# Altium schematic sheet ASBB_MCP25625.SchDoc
size A4
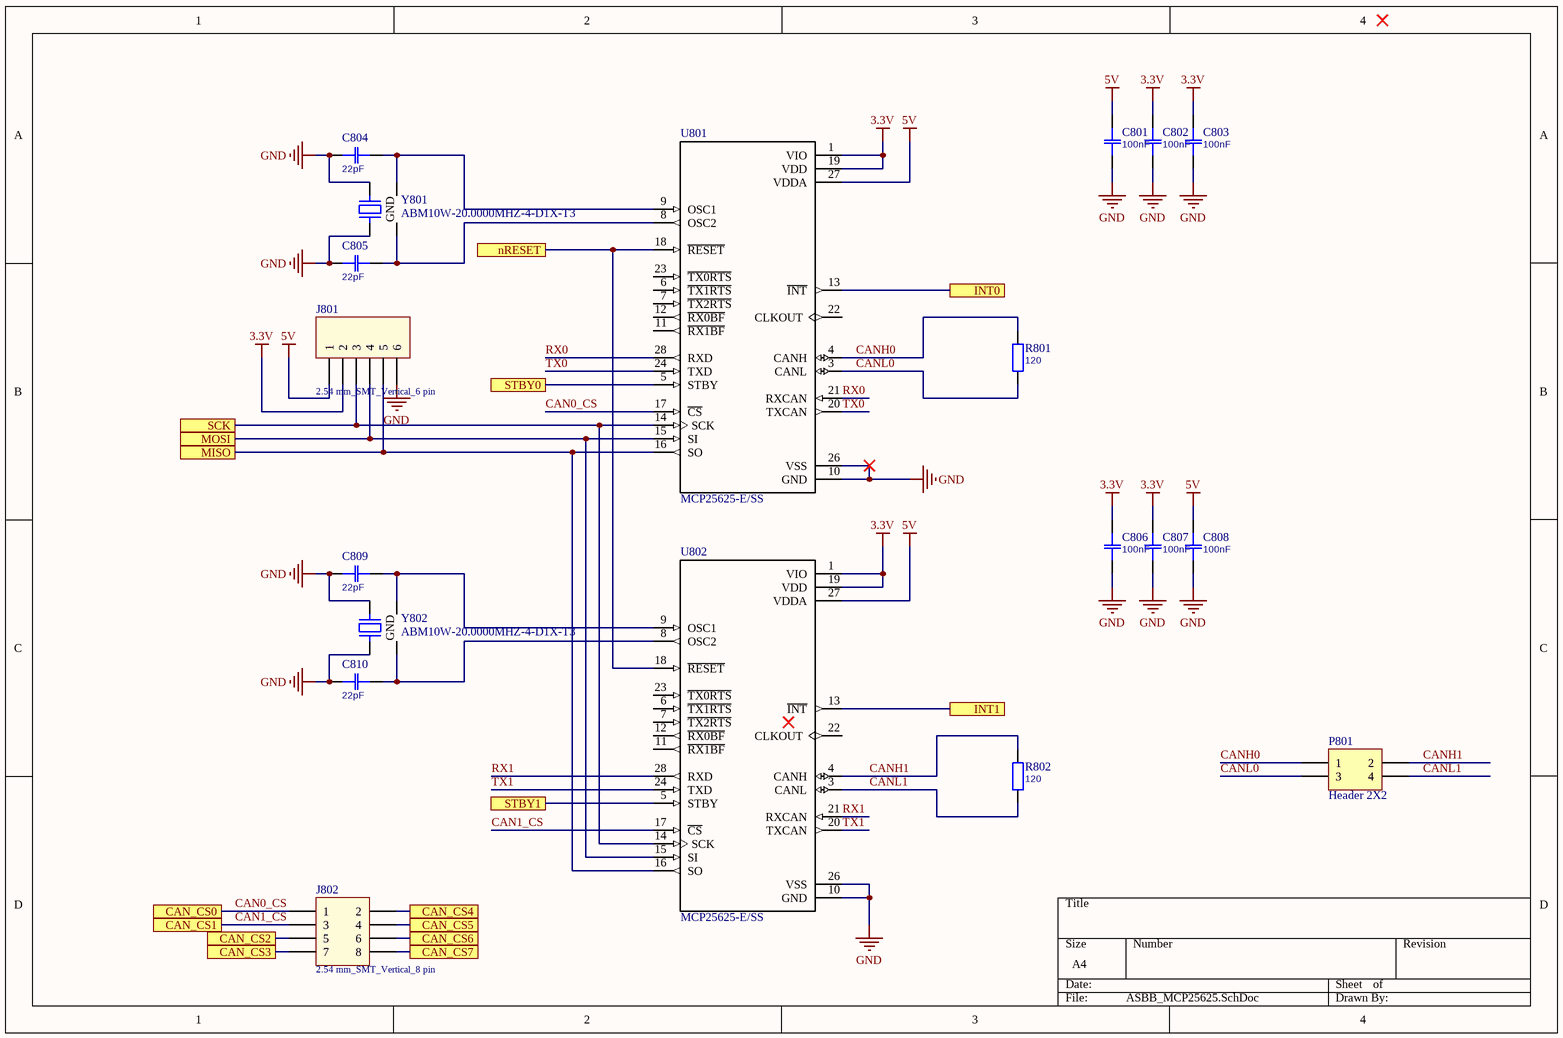
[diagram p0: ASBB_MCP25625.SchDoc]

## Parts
C801  100nF  [0603]
C802  100nF  [0603]
C803  100nF  [0603]
C804  22pF  [0603]
C805  22pF  [0603]
C806  100nF  [0603]
C807  100nF  [0603]
C808  100nF  [0603]
C809  22pF  [0603]
C810  22pF  [0603]
J801  2.54 mm_SMT_Vertical_6 pin  [61000611921]
J802  2.54 mm_SMT_Vertical_8 pin  [61000821821]
P801  Header 2X2  [HDR2X2]
R801  120  [0603]
R802  120  [0603]
U801  MCP25625-E/SS  [SOP65P780X200-28N]
U802  MCP25625-E/SS  [SOP65P780X200-28N]
Y801  ABM10W-20.0000MHZ-4-D1X-T3  [ABRACON ABM10]
Y802  ABM10W-20.0000MHZ-4-D1X-T3  [ABRACON ABM10]

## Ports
CAN_CS0, CAN_CS1, CAN_CS2, CAN_CS3, CAN_CS4, CAN_CS5, CAN_CS6, CAN_CS7, INT0, INT1, MISO, MOSI, nRESET, SCK, STBY0, STBY1

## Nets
3.3V: C802.2 C803.2 C806.2 C807.2 J801.2 U801.1(VIO) U801.19(VDD) U802.1(VIO) U802.19(VDD)
5V: C801.1 C808.2 J801.1 U801.27(VDDA) U802.27(VDDA)
GND: C801.2 C802.1 C803.1 C804.2 C805.2 C806.1 C807.1 C808.1 C809.2 C810.2 J801.6 U801.10(GND) U801.26(VSS) U802.10(GND) U802.26(VSS) Y801.1 Y801.3 Y802.1 Y802.3
CAN0_CS: J802.1 U801.17(~{CS}) ; port CAN_CS0
CAN1_CS: J802.3 U802.17(~{CS}) ; port CAN_CS1
CAN_CS2: J802.5 ; port CAN_CS2
CAN_CS3: J802.7 ; port CAN_CS3
CAN_CS4: J802.2 ; port CAN_CS4
CAN_CS5: J802.4 ; port CAN_CS5
CAN_CS6: J802.6 ; port CAN_CS6
CAN_CS7: J802.8 ; port CAN_CS7
CANH0: P801.1 R801.2 U801.4(CANH)
CANH1: P801.2 R802.2 U802.4(CANH)
CANL0: P801.3 R801.1 U801.3(CANL)
CANL1: P801.4 R802.1 U802.3(CANL)
INT0: U801.13(~{INT}) ; port INT0
INT1: U802.13(~{INT}) ; port INT1
MISO: J801.5 U801.16(SO) U802.16(SO) ; port MISO
MOSI: J801.4 U801.15(SI) U802.15(SI) ; port MOSI
nRESET: U801.18(~{RESET}) U802.18(~{RESET}) ; port nRESET
RX0: U801.21(RXCAN) U801.28(RXD)
RX1: U802.21(RXCAN) U802.28(RXD)
SCK: J801.3 U801.14(SCK) U802.14(SCK) ; port SCK
STBY0: U801.5(STBY) ; port STBY0
STBY1: U802.5(STBY) ; port STBY1
TX0: U801.20(TXCAN) U801.24(TXD)
TX1: U802.20(TXCAN) U802.24(TXD)
NetC804_1: C804.1 U801.9(OSC1) Y801.2(GND)
NetC805_1: C805.1 U801.8(OSC2) Y801.4(GND)
NetC809_1: C809.1 U802.9(OSC1) Y802.2(GND)
NetC810_1: C810.1 U802.8(OSC2) Y802.4(GND)

Not connected (* = marked no-connect by the designer): U801 6(~{TX1RTS}) 7(~{TX2RTS}) 11(~{RX1BF}) 12(~{RX0BF}) 22(CLKOUT) 23(~{TX0RTS}); U802 6(~{TX1RTS}) 7(~{TX2RTS}) 11(~{RX1BF}) 12(~{RX0BF}) 22(CLKOUT) 23(~{TX0RTS})

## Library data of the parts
C801-C810 = Capacitor
J801 = 61000611921: Socket Header WR-PHD, Pitch 2.54 mm, SMT, Vertical, single row, 6 pin; Rated Current: 3 A; Pin Number: 6; Pitch: 2.54 mm; Working Voltage: 250 VAC; Contact Resistance: 20 mOhm; Insulation Resistance: >1000 MOhm
J802 = 61000821821: Socket Header WR-PHD, Pitch 2.54 mm, SMT, Vertical, dual row, 8 pin; Rated Current: 3 A; Pin Number: 8; Pitch: 2.54 mm; Working Voltage: 250 VAC; Contact Resistance: 20 mOhm; Insulation Resistance: >1000 MOhm
P801 = Header 2X2: Header, 2-Pin, Dual row
R801 R802 = Resistor
U801 U802 = MCP25625-E/SS: 28 SSOP .209in TUBECAN Controller with Integrated Transceiver; MF: Microchip
Y801 Y802 = Abracon Crystal ABM10: SMT Crystal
